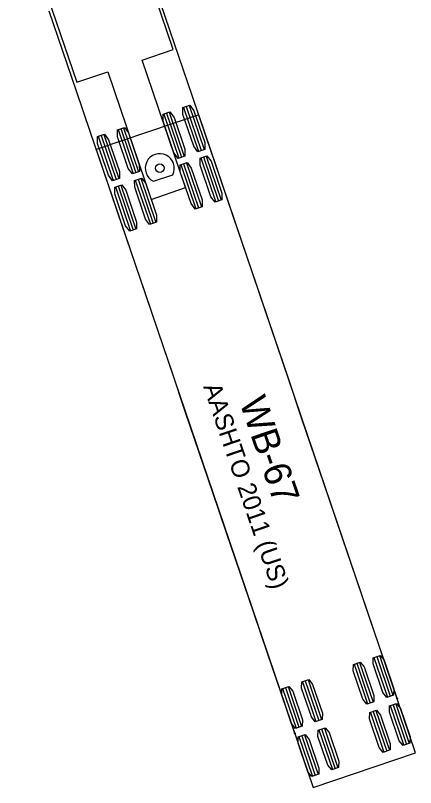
# Model space of a CAD drawing. Extents: x 916040 to 917457, y 328936 to 330267.
# Drawn here: x 916917.5 to 916949, y 328935.5 to 328996.3 of the extents above; entities that cross this region are included whole.
import ezdxf

# ---------------------------------------------------------------- set-up
doc = ezdxf.new("R2010")
doc.units = 0
doc.layers.add('NB_RightontoRoute25_WB67', color=7, linetype='Continuous')
doc.layers.add('NB_ThruontoManchester_WB67', color=7, linetype='Continuous')

msp = doc.modelspace()

# ---------------------------------------------------------------- linework, layer by layer
at = {"layer": 'NB_RightontoRoute25_WB67'}
for p, q in [((916929.951, 328993.567), (916925.124, 329007.769)), ((916917.55, 329005.195), (916922.377, 328990.993)), ((916927.521, 328992.741), (916929.951, 328993.567)), ((916930.932, 328982.705), (916927.521, 328992.741)), ((916922.377, 328990.993), (916924.807, 328991.819)), ((916924.807, 328991.819), (916928.218, 328981.783)), ((916931.204, 328989.17), (916932.384, 328985.698)), ((916929.425, 328988.565), (916930.604, 328985.093)), ((916929.642, 328988.639), (916930.821, 328985.167)), ((916930.77, 328989.022), (916931.95, 328985.551)), ((916930.987, 328989.096), (916932.167, 328985.624)), ((916931.958, 328988.44), (916923.91, 328985.705)), ((916929.208, 328988.491), (916930.388, 328985.02)), ((916949.013, 328938.259), (916931.958, 328988.44)), ((916925.842, 328987.348), (916927.022, 328983.876)), ((916926.059, 328987.421), (916927.239, 328983.95)), ((916924.063, 328986.743), (916925.243, 328983.271)), ((916924.28, 328986.817), (916925.46, 328983.345)), ((916924.497, 328986.89), (916925.677, 328983.419)), ((916925.626, 328987.274), (916926.805, 328983.802)), ((916923.91, 328985.705), (916940.965, 328935.524)), ((916923.91, 328985.705), (916923.91, 328985.705)), ((916932.121, 328985.046), (916933.301, 328981.574)), ((916932.338, 328985.119), (916933.518, 328981.648)), ((916932.555, 328985.193), (916933.735, 328981.722)), ((916930.559, 328984.515), (916931.739, 328981.043)), ((916930.776, 328984.588), (916931.956, 328981.117)), ((916930.993, 328984.662), (916932.173, 328981.191)), ((916928.394, 328983.207), (916929.924, 328983.727)), ((916926.977, 328983.297), (916928.157, 328979.826)), ((916927.194, 328983.371), (916928.374, 328979.899)), ((916927.411, 328983.445), (916928.591, 328979.973)), ((916925.415, 328982.766), (916926.595, 328979.295)), ((916925.632, 328982.84), (916926.812, 328979.368)), ((916925.849, 328982.914), (916927.029, 328979.442)), ((916928.218, 328981.783), (916930.932, 328982.705)), ((916945.739, 328945.755), (916946.801, 328942.63)), ((916945.956, 328945.828), (916947.018, 328942.704)), ((916946.173, 328945.902), (916947.235, 328942.778)), ((916944.177, 328945.224), (916945.239, 328942.099)), ((916944.394, 328945.297), (916945.456, 328942.173)), ((916944.611, 328945.371), (916945.673, 328942.247)), ((916940.122, 328943.845), (916941.184, 328940.721)), ((916940.339, 328943.919), (916941.401, 328940.795)), ((916940.556, 328943.993), (916941.617, 328940.868)), ((916938.559, 328943.314), (916939.621, 328940.19)), ((916938.776, 328943.388), (916939.838, 328940.264)), ((916938.993, 328943.462), (916940.055, 328940.337)), ((916947.027, 328941.967), (916948.088, 328938.843)), ((916947.243, 328942.041), (916948.305, 328938.917)), ((916947.46, 328942.115), (916948.522, 328938.99)), ((916945.464, 328941.436), (916946.526, 328938.312)), ((916945.681, 328941.51), (916946.743, 328938.386)), ((916945.898, 328941.584), (916946.96, 328938.459)), ((916941.409, 328940.058), (916942.471, 328936.934)), ((916941.626, 328940.132), (916942.688, 328937.007)), ((916941.843, 328940.206), (916942.905, 328937.081)), ((916939.847, 328939.527), (916940.908, 328936.403)), ((916940.064, 328939.601), (916941.125, 328936.476)), ((916940.28, 328939.675), (916941.342, 328936.55)), ((916940.965, 328935.524), (916949.013, 328938.259))]:
    msp.add_line(p, q, dxfattribs=at)
for points in [[(916947.565, 328942.52), (916946.492, 328945.676), (916945.419, 328948.832), (916944.347, 328951.988), (916943.274, 328955.145), (916942.201, 328958.301), (916941.129, 328961.457), (916940.056, 328964.613), (916938.983, 328967.769), (916937.911, 328970.925), (916936.838, 328974.082), (916935.765, 328977.238), (916934.693, 328980.394), (916933.62, 328983.55), (916932.547, 328986.706), (916931.475, 328989.862), (916930.402, 328993.018), (916929.329, 328996.175), (916928.256, 328999.331)], [(916939.517, 328939.785), (916938.444, 328942.941), (916937.372, 328946.097), (916936.299, 328949.253), (916935.226, 328952.409), (916934.154, 328955.566), (916933.081, 328958.722), (916932.008, 328961.878), (916930.935, 328965.034), (916929.863, 328968.19), (916928.79, 328971.346), (916927.717, 328974.502), (916926.645, 328977.659), (916925.572, 328980.815), (916924.499, 328983.971), (916923.427, 328987.127), (916922.354, 328990.283), (916921.281, 328993.439), (916920.209, 328996.595)]]:
    msp.add_lwpolyline(points, dxfattribs=at)
for points in [[(916930.716, 328989.004), (916931.258, 328989.188), (916931.586, 328988.758), (916932.435, 328986.258), (916932.438, 328985.716), (916931.896, 328985.532), (916931.568, 328985.963), (916930.718, 328988.463)], [(916929.154, 328988.473), (916929.695, 328988.657), (916930.024, 328988.227), (916930.873, 328985.727), (916930.875, 328985.185), (916930.334, 328985.001), (916930.005, 328985.432), (916929.156, 328987.932)], [(916925.572, 328987.256), (916926.113, 328987.44), (916926.442, 328987.009), (916927.291, 328984.51), (916927.293, 328983.968), (916926.752, 328983.784), (916926.423, 328984.215), (916925.574, 328986.714)], [(916924.009, 328986.725), (916924.551, 328986.909), (916924.879, 328986.478), (916925.729, 328983.979), (916925.731, 328983.437), (916925.189, 328983.253), (916924.861, 328983.684), (916924.011, 328986.183)], [(916932.068, 328985.027), (916932.609, 328985.211), (916932.937, 328984.781), (916933.787, 328982.281), (916933.789, 328981.74), (916933.247, 328981.556), (916932.919, 328981.986), (916932.07, 328984.486)], [(916930.505, 328984.496), (916931.047, 328984.681), (916931.375, 328984.25), (916932.225, 328981.75), (916932.227, 328981.209), (916931.685, 328981.025), (916931.357, 328981.455), (916930.507, 328983.955)], [(916926.923, 328983.279), (916927.465, 328983.463), (916927.793, 328983.032), (916928.643, 328980.533), (916928.645, 328979.991), (916928.103, 328979.807), (916927.775, 328980.238), (916926.925, 328982.738)], [(916925.361, 328982.748), (916925.903, 328982.932), (916926.231, 328982.502), (916927.08, 328980.002), (916927.082, 328979.46), (916926.541, 328979.276), (916926.213, 328979.707), (916925.363, 328982.207)], [(916945.686, 328945.736), (916946.227, 328945.92), (916946.539, 328945.538), (916947.304, 328943.289), (916947.289, 328942.796), (916946.747, 328942.612), (916946.436, 328942.994), (916945.671, 328945.243)], [(916944.123, 328945.205), (916944.665, 328945.389), (916944.977, 328945.007), (916945.741, 328942.758), (916945.727, 328942.265), (916945.185, 328942.081), (916944.873, 328942.463), (916944.109, 328944.713)], [(916940.068, 328943.827), (916940.609, 328944.011), (916940.921, 328943.629), (916941.686, 328941.38), (916941.671, 328940.887), (916941.13, 328940.703), (916940.818, 328941.085), (916940.053, 328943.334)], [(916938.506, 328943.296), (916939.047, 328943.48), (916939.359, 328943.098), (916940.124, 328940.849), (916940.109, 328940.356), (916939.567, 328940.172), (916939.256, 328940.554), (916938.491, 328942.803)], [(916946.973, 328941.949), (916947.514, 328942.133), (916947.826, 328941.751), (916948.591, 328939.502), (916948.576, 328939.009), (916948.035, 328938.825), (916947.723, 328939.207), (916946.958, 328941.456)], [(916945.41, 328941.418), (916945.952, 328941.602), (916946.264, 328941.22), (916947.028, 328938.971), (916947.014, 328938.478), (916946.472, 328938.294), (916946.161, 328938.676), (916945.396, 328940.925)], [(916941.355, 328940.04), (916941.897, 328940.224), (916942.208, 328939.842), (916942.973, 328937.592), (916942.958, 328937.099), (916942.417, 328936.915), (916942.105, 328937.297), (916941.34, 328939.547)], [(916939.793, 328939.509), (916940.334, 328939.693), (916940.646, 328939.311), (916941.411, 328937.061), (916941.396, 328936.568), (916940.855, 328936.384), (916940.543, 328936.766), (916939.778, 328939.016)]]:
    msp.add_lwpolyline(points, close=True, dxfattribs=at)
for centre, radius in [((916928.899, 328984.232), 0.34), ((916947.565, 328942.52), 0.0417), ((916939.517, 328939.785), 0.0417)]:
    msp.add_circle(centre, radius, dxfattribs=at)
msp.add_arc((916928.899, 328984.232), 1.143, 333.77146, 243.77146, dxfattribs=at)
at = {"layer": 'NB_ThruontoManchester_WB67'}
for p, q in [((916929.951, 328993.567), (916925.124, 329007.769)), ((916929.951, 328993.567), (916925.124, 329007.769)), ((916917.55, 329005.195), (916922.377, 328990.993)), ((916917.55, 329005.195), (916922.377, 328990.993)), ((916927.521, 328992.741), (916929.951, 328993.567)), ((916927.521, 328992.741), (916929.951, 328993.567)), ((916930.932, 328982.705), (916927.521, 328992.741)), ((916930.932, 328982.705), (916927.521, 328992.741)), ((916922.377, 328990.993), (916924.807, 328991.819)), ((916922.377, 328990.993), (916924.807, 328991.819)), ((916924.807, 328991.819), (916928.218, 328981.783)), ((916924.807, 328991.819), (916928.218, 328981.783)), ((916931.204, 328989.17), (916932.384, 328985.698)), ((916931.204, 328989.17), (916932.384, 328985.698)), ((916929.425, 328988.565), (916930.604, 328985.093)), ((916929.425, 328988.565), (916930.604, 328985.093)), ((916929.642, 328988.639), (916930.821, 328985.167)), ((916929.642, 328988.639), (916930.821, 328985.167)), ((916930.77, 328989.022), (916931.95, 328985.551)), ((916930.77, 328989.022), (916931.95, 328985.551)), ((916930.987, 328989.096), (916932.167, 328985.624)), ((916930.987, 328989.096), (916932.167, 328985.624)), ((916931.958, 328988.44), (916923.91, 328985.705)), ((916931.958, 328988.44), (916923.91, 328985.705)), ((916929.208, 328988.491), (916930.388, 328985.02)), ((916929.208, 328988.491), (916930.388, 328985.02)), ((916949.013, 328938.259), (916931.958, 328988.44)), ((916949.013, 328938.259), (916931.958, 328988.44)), ((916925.842, 328987.348), (916927.022, 328983.876)), ((916925.842, 328987.348), (916927.022, 328983.876)), ((916926.059, 328987.421), (916927.239, 328983.95)), ((916926.059, 328987.421), (916927.239, 328983.95)), ((916924.063, 328986.743), (916925.243, 328983.271)), ((916924.063, 328986.743), (916925.243, 328983.271)), ((916924.28, 328986.817), (916925.46, 328983.345)), ((916924.28, 328986.817), (916925.46, 328983.345)), ((916924.497, 328986.89), (916925.677, 328983.419)), ((916924.497, 328986.89), (916925.677, 328983.419)), ((916925.626, 328987.274), (916926.805, 328983.802)), ((916925.626, 328987.274), (916926.805, 328983.802)), ((916923.91, 328985.705), (916940.965, 328935.524)), ((916923.91, 328985.705), (916923.91, 328985.705)), ((916923.91, 328985.705), (916940.965, 328935.524)), ((916923.91, 328985.705), (916923.91, 328985.705)), ((916932.121, 328985.046), (916933.301, 328981.574)), ((916932.121, 328985.046), (916933.301, 328981.574)), ((916932.338, 328985.119), (916933.518, 328981.648)), ((916932.338, 328985.119), (916933.518, 328981.648)), ((916932.555, 328985.193), (916933.735, 328981.722)), ((916932.555, 328985.193), (916933.735, 328981.722)), ((916930.559, 328984.515), (916931.739, 328981.043)), ((916930.559, 328984.515), (916931.739, 328981.043)), ((916930.776, 328984.588), (916931.956, 328981.117)), ((916930.776, 328984.588), (916931.956, 328981.117)), ((916930.993, 328984.662), (916932.173, 328981.191)), ((916930.993, 328984.662), (916932.173, 328981.191)), ((916928.394, 328983.207), (916929.924, 328983.727)), ((916928.394, 328983.207), (916929.924, 328983.727)), ((916926.977, 328983.297), (916928.157, 328979.826)), ((916926.977, 328983.297), (916928.157, 328979.826)), ((916927.194, 328983.371), (916928.374, 328979.899)), ((916927.194, 328983.371), (916928.374, 328979.899)), ((916927.411, 328983.445), (916928.591, 328979.973)), ((916927.411, 328983.445), (916928.591, 328979.973)), ((916925.415, 328982.766), (916926.595, 328979.295)), ((916925.415, 328982.766), (916926.595, 328979.295)), ((916925.632, 328982.84), (916926.812, 328979.368)), ((916925.632, 328982.84), (916926.812, 328979.368)), ((916925.849, 328982.914), (916927.029, 328979.442)), ((916925.849, 328982.914), (916927.029, 328979.442)), ((916928.218, 328981.783), (916930.932, 328982.705)), ((916928.218, 328981.783), (916930.932, 328982.705)), ((916945.739, 328945.755), (916946.801, 328942.63)), ((916945.739, 328945.755), (916946.801, 328942.63)), ((916945.956, 328945.828), (916947.018, 328942.704)), ((916945.956, 328945.828), (916947.018, 328942.704)), ((916946.173, 328945.902), (916947.235, 328942.778)), ((916946.173, 328945.902), (916947.235, 328942.778)), ((916944.177, 328945.224), (916945.239, 328942.099)), ((916944.177, 328945.224), (916945.239, 328942.099)), ((916944.394, 328945.297), (916945.456, 328942.173)), ((916944.394, 328945.297), (916945.456, 328942.173)), ((916944.611, 328945.371), (916945.673, 328942.247)), ((916944.611, 328945.371), (916945.673, 328942.247)), ((916940.122, 328943.845), (916941.184, 328940.721)), ((916940.122, 328943.845), (916941.184, 328940.721)), ((916940.339, 328943.919), (916941.401, 328940.795)), ((916940.339, 328943.919), (916941.401, 328940.795)), ((916940.556, 328943.993), (916941.617, 328940.868)), ((916940.556, 328943.993), (916941.617, 328940.868)), ((916938.559, 328943.314), (916939.621, 328940.19)), ((916938.559, 328943.314), (916939.621, 328940.19)), ((916938.776, 328943.388), (916939.838, 328940.264)), ((916938.776, 328943.388), (916939.838, 328940.264)), ((916938.993, 328943.462), (916940.055, 328940.337)), ((916938.993, 328943.462), (916940.055, 328940.337)), ((916947.027, 328941.967), (916948.088, 328938.843)), ((916947.027, 328941.967), (916948.088, 328938.843)), ((916947.243, 328942.041), (916948.305, 328938.917)), ((916947.243, 328942.041), (916948.305, 328938.917)), ((916947.46, 328942.115), (916948.522, 328938.99)), ((916947.46, 328942.115), (916948.522, 328938.99)), ((916945.464, 328941.436), (916946.526, 328938.312)), ((916945.464, 328941.436), (916946.526, 328938.312)), ((916945.681, 328941.51), (916946.743, 328938.386)), ((916945.681, 328941.51), (916946.743, 328938.386)), ((916945.898, 328941.584), (916946.96, 328938.459)), ((916945.898, 328941.584), (916946.96, 328938.459)), ((916941.409, 328940.058), (916942.471, 328936.934)), ((916941.409, 328940.058), (916942.471, 328936.934)), ((916941.626, 328940.132), (916942.688, 328937.007)), ((916941.626, 328940.132), (916942.688, 328937.007)), ((916941.843, 328940.206), (916942.905, 328937.081)), ((916941.843, 328940.206), (916942.905, 328937.081)), ((916939.847, 328939.527), (916940.908, 328936.403)), ((916939.847, 328939.527), (916940.908, 328936.403)), ((916940.064, 328939.601), (916941.125, 328936.476)), ((916940.064, 328939.601), (916941.125, 328936.476)), ((916940.28, 328939.675), (916941.342, 328936.55)), ((916940.28, 328939.675), (916941.342, 328936.55)), ((916940.965, 328935.524), (916949.013, 328938.259)), ((916940.965, 328935.524), (916949.013, 328938.259))]:
    msp.add_line(p, q, dxfattribs=at)
for points in [[(916930.716, 328989.004), (916931.258, 328989.188), (916931.586, 328988.758), (916932.435, 328986.258), (916932.438, 328985.716), (916931.896, 328985.532), (916931.568, 328985.963), (916930.718, 328988.463)], [(916930.716, 328989.004), (916931.258, 328989.188), (916931.586, 328988.758), (916932.435, 328986.258), (916932.438, 328985.716), (916931.896, 328985.532), (916931.568, 328985.963), (916930.718, 328988.463)], [(916929.154, 328988.473), (916929.695, 328988.657), (916930.024, 328988.227), (916930.873, 328985.727), (916930.875, 328985.185), (916930.334, 328985.001), (916930.005, 328985.432), (916929.156, 328987.932)], [(916929.154, 328988.473), (916929.695, 328988.657), (916930.024, 328988.227), (916930.873, 328985.727), (916930.875, 328985.185), (916930.334, 328985.001), (916930.005, 328985.432), (916929.156, 328987.932)], [(916925.572, 328987.256), (916926.113, 328987.44), (916926.442, 328987.009), (916927.291, 328984.51), (916927.293, 328983.968), (916926.752, 328983.784), (916926.423, 328984.215), (916925.574, 328986.714)], [(916925.572, 328987.256), (916926.113, 328987.44), (916926.442, 328987.009), (916927.291, 328984.51), (916927.293, 328983.968), (916926.752, 328983.784), (916926.423, 328984.215), (916925.574, 328986.714)], [(916924.009, 328986.725), (916924.551, 328986.909), (916924.879, 328986.478), (916925.729, 328983.979), (916925.731, 328983.437), (916925.189, 328983.253), (916924.861, 328983.684), (916924.011, 328986.183)], [(916924.009, 328986.725), (916924.551, 328986.909), (916924.879, 328986.478), (916925.729, 328983.979), (916925.731, 328983.437), (916925.189, 328983.253), (916924.861, 328983.684), (916924.011, 328986.183)], [(916932.068, 328985.027), (916932.609, 328985.211), (916932.937, 328984.781), (916933.787, 328982.281), (916933.789, 328981.74), (916933.247, 328981.556), (916932.919, 328981.986), (916932.07, 328984.486)], [(916932.068, 328985.027), (916932.609, 328985.211), (916932.937, 328984.781), (916933.787, 328982.281), (916933.789, 328981.74), (916933.247, 328981.556), (916932.919, 328981.986), (916932.07, 328984.486)], [(916930.505, 328984.496), (916931.047, 328984.681), (916931.375, 328984.25), (916932.225, 328981.75), (916932.227, 328981.209), (916931.685, 328981.025), (916931.357, 328981.455), (916930.507, 328983.955)], [(916930.505, 328984.496), (916931.047, 328984.681), (916931.375, 328984.25), (916932.225, 328981.75), (916932.227, 328981.209), (916931.685, 328981.025), (916931.357, 328981.455), (916930.507, 328983.955)], [(916926.923, 328983.279), (916927.465, 328983.463), (916927.793, 328983.032), (916928.643, 328980.533), (916928.645, 328979.991), (916928.103, 328979.807), (916927.775, 328980.238), (916926.925, 328982.738)], [(916926.923, 328983.279), (916927.465, 328983.463), (916927.793, 328983.032), (916928.643, 328980.533), (916928.645, 328979.991), (916928.103, 328979.807), (916927.775, 328980.238), (916926.925, 328982.738)], [(916925.361, 328982.748), (916925.903, 328982.932), (916926.231, 328982.502), (916927.08, 328980.002), (916927.082, 328979.46), (916926.541, 328979.276), (916926.213, 328979.707), (916925.363, 328982.207)], [(916925.361, 328982.748), (916925.903, 328982.932), (916926.231, 328982.502), (916927.08, 328980.002), (916927.082, 328979.46), (916926.541, 328979.276), (916926.213, 328979.707), (916925.363, 328982.207)], [(916945.686, 328945.736), (916946.227, 328945.92), (916946.539, 328945.538), (916947.304, 328943.289), (916947.289, 328942.796), (916946.747, 328942.612), (916946.436, 328942.994), (916945.671, 328945.243)], [(916945.686, 328945.736), (916946.227, 328945.92), (916946.539, 328945.538), (916947.304, 328943.289), (916947.289, 328942.796), (916946.747, 328942.612), (916946.436, 328942.994), (916945.671, 328945.243)], [(916944.123, 328945.205), (916944.665, 328945.389), (916944.977, 328945.007), (916945.741, 328942.758), (916945.727, 328942.265), (916945.185, 328942.081), (916944.873, 328942.463), (916944.109, 328944.713)], [(916944.123, 328945.205), (916944.665, 328945.389), (916944.977, 328945.007), (916945.741, 328942.758), (916945.727, 328942.265), (916945.185, 328942.081), (916944.873, 328942.463), (916944.109, 328944.713)], [(916940.068, 328943.827), (916940.609, 328944.011), (916940.921, 328943.629), (916941.686, 328941.38), (916941.671, 328940.887), (916941.13, 328940.703), (916940.818, 328941.085), (916940.053, 328943.334)], [(916940.068, 328943.827), (916940.609, 328944.011), (916940.921, 328943.629), (916941.686, 328941.38), (916941.671, 328940.887), (916941.13, 328940.703), (916940.818, 328941.085), (916940.053, 328943.334)], [(916938.506, 328943.296), (916939.047, 328943.48), (916939.359, 328943.098), (916940.124, 328940.849), (916940.109, 328940.356), (916939.567, 328940.172), (916939.256, 328940.554), (916938.491, 328942.803)], [(916938.506, 328943.296), (916939.047, 328943.48), (916939.359, 328943.098), (916940.124, 328940.849), (916940.109, 328940.356), (916939.567, 328940.172), (916939.256, 328940.554), (916938.491, 328942.803)], [(916946.973, 328941.949), (916947.514, 328942.133), (916947.826, 328941.751), (916948.591, 328939.502), (916948.576, 328939.009), (916948.035, 328938.825), (916947.723, 328939.207), (916946.958, 328941.456)], [(916946.973, 328941.949), (916947.514, 328942.133), (916947.826, 328941.751), (916948.591, 328939.502), (916948.576, 328939.009), (916948.035, 328938.825), (916947.723, 328939.207), (916946.958, 328941.456)], [(916945.41, 328941.418), (916945.952, 328941.602), (916946.264, 328941.22), (916947.028, 328938.971), (916947.014, 328938.478), (916946.472, 328938.294), (916946.161, 328938.676), (916945.396, 328940.925)], [(916945.41, 328941.418), (916945.952, 328941.602), (916946.264, 328941.22), (916947.028, 328938.971), (916947.014, 328938.478), (916946.472, 328938.294), (916946.161, 328938.676), (916945.396, 328940.925)], [(916941.355, 328940.04), (916941.897, 328940.224), (916942.208, 328939.842), (916942.973, 328937.592), (916942.958, 328937.099), (916942.417, 328936.915), (916942.105, 328937.297), (916941.34, 328939.547)], [(916941.355, 328940.04), (916941.897, 328940.224), (916942.208, 328939.842), (916942.973, 328937.592), (916942.958, 328937.099), (916942.417, 328936.915), (916942.105, 328937.297), (916941.34, 328939.547)], [(916939.793, 328939.509), (916940.334, 328939.693), (916940.646, 328939.311), (916941.411, 328937.061), (916941.396, 328936.568), (916940.855, 328936.384), (916940.543, 328936.766), (916939.778, 328939.016)], [(916939.793, 328939.509), (916940.334, 328939.693), (916940.646, 328939.311), (916941.411, 328937.061), (916941.396, 328936.568), (916940.855, 328936.384), (916940.543, 328936.766), (916939.778, 328939.016)]]:
    msp.add_lwpolyline(points, close=True, dxfattribs=at)
msp.add_circle((916928.899, 328984.232), 0.34, dxfattribs=at)
msp.add_circle((916928.899, 328984.232), 0.34, dxfattribs=at)
msp.add_arc((916928.899, 328984.232), 1.143, 333.77146, 243.77146, dxfattribs=at)
msp.add_arc((916928.899, 328984.232), 1.143, 333.77146, 243.77146, dxfattribs=at)

# ---------------------------------------------------------------- texts
at = {"layer": 'NB_RightontoRoute25_WB67'}
for s, height, p in [('AASHTO 2011 (US)', 1.41667, (916932.302, 328967.066)), ('WB-67', 2.125, (916935.143, 328965.862))]:
    msp.add_text(s, height=height, rotation=288.77146, dxfattribs=at).set_placement(p)
at = {"layer": 'NB_ThruontoManchester_WB67'}
for s, height, p in [('AASHTO 2011 (US)', 1.41667, (916932.302, 328967.066)), ('AASHTO 2011 (US)', 1.41667, (916932.302, 328967.066)), ('WB-67', 2.125, (916935.143, 328965.862)), ('WB-67', 2.125, (916935.143, 328965.862))]:
    msp.add_text(s, height=height, rotation=288.77146, dxfattribs=at).set_placement(p)

doc.saveas('drawing.dxf')
